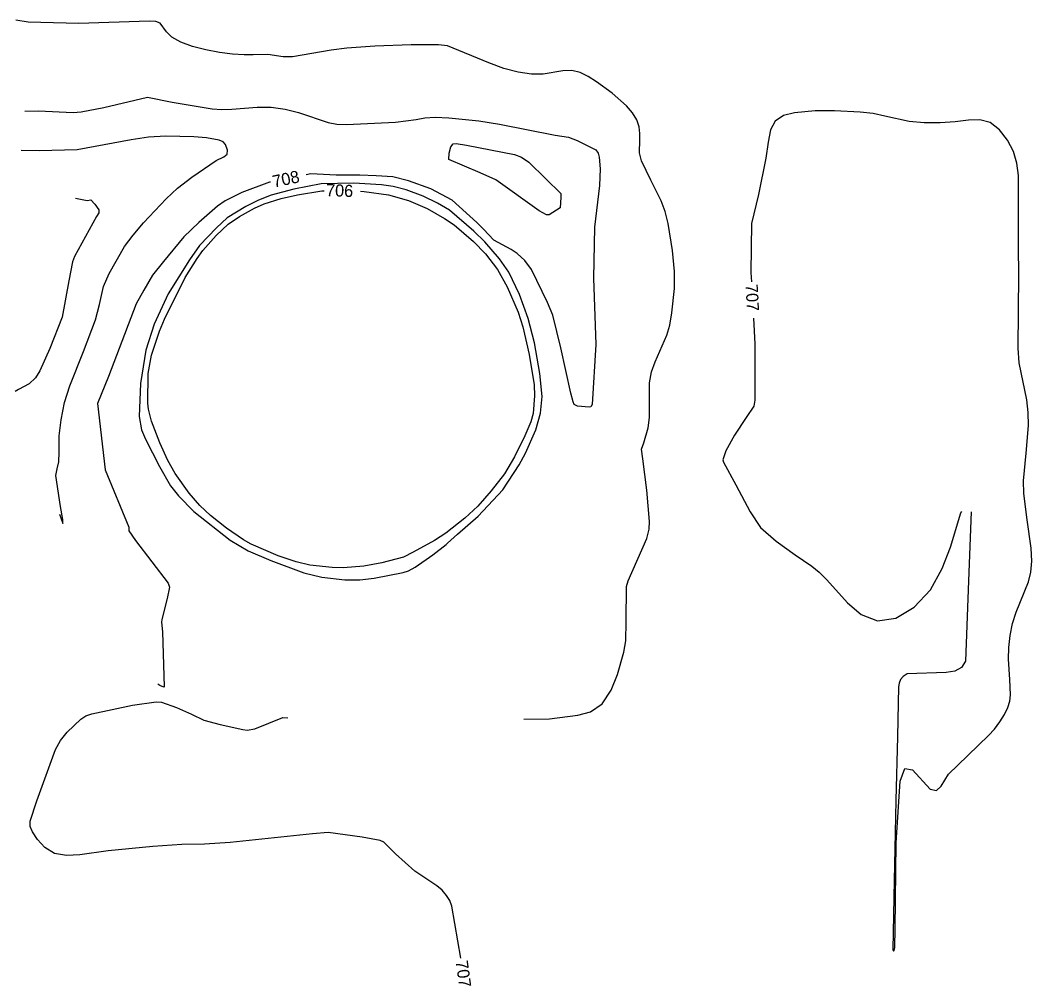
# Model space of a CAD drawing. Extents: x -291892836 to 2945206, y -477993085 to 1832792.
# Drawn here: x 1849119 to 1849452, y 544307.9 to 544625.9 of the extents above; entities that cross this region are included whole.
import ezdxf

# ---------------------------------------------------------------- set-up
doc = ezdxf.new("R2010")
doc.units = 0
doc.layers.add('DT_X_Contour_Minor', color=7, linetype='Continuous')
doc.layers.add('Level 19', color=7, linetype='Continuous')

msp = doc.modelspace()

# ---------------------------------------------------------------- linework, layer by layer
at = {"layer": 'DT_X_Contour_Minor'}
for points in [[(1849284.82, 544395.63), (1849293.23, 544395.79), (1849302.58, 544396.95), (1849306.71, 544398.13), (1849310.6, 544400.76), (1849313.6, 544405.19), (1849315.7, 544410.37), (1849317.7, 544417.73), (1849318.36, 544421.49), (1849318.47, 544427.89), (1849318.65, 544439.34), (1849319.14, 544441.24), (1849325.33, 544455.16), (1849326.1, 544458.21), (1849326.23, 544460.8), (1849325.34, 544471.14), (1849323.98, 544481.36), (1849323.6, 544484.56), (1849324.27, 544486.69), (1849325.76, 544491.63), (1849326.22, 544495.02), (1849326.17, 544506.42), (1849326.88, 544510.03), (1849328.05, 544513.38), (1849331.85, 544522.09), (1849332.83, 544525.42), (1849333.59, 544529.45), (1849334.43, 544537.52), (1849334.43, 544543.14), (1849333.73, 544550.07), (1849332.33, 544558.9), (1849331.31, 544562.82), (1849330.04, 544566.36), (1849326.66, 544573.22), (1849323.58, 544579.59), (1849322.95, 544582.14), (1849322.96, 544586.46), (1849323.01, 544588.59), (1849322.76, 544590.79), (1849322, 544593.05), (1849320.58, 544595.35), (1849318.62, 544597.63), (1849313.89, 544601.87), (1849308.71, 544605.61), (1849306.05, 544607.31), (1849303.34, 544608.65), (1849300.57, 544609.32), (1849297.71, 544609.17), (1849291.21, 544608.07), (1849287.32, 544608.09), (1849282.99, 544608.73), (1849278.28, 544609.99), (1849273.32, 544611.81), (1849259.65, 544617.42), (1849256.7, 544617.72), (1849247.77, 544617.77), (1849235.73, 544617.36), (1849226.6, 544616.68), (1849221.39, 544616.03), (1849208.7, 544613.74), (1849205.6, 544613.79), (1849200.56, 544614.52), (1849195.76, 544614.49), (1849192.73, 544614.47), (1849188.96, 544614.71), (1849184.67, 544615.26), (1849180.15, 544616.11), (1849175.76, 544617.25), (1849171.89, 544618.65), (1849168.94, 544620.26), (1849167.16, 544622.01), (1849165.1, 544624.86), (1849163.64, 544625.46), (1849161.49, 544625.59), (1849138.35, 544624.8), (1849121.69, 544625.24), (1849117.53, 544625.85)], [(1849120.55, 544595.93), (1849125.06, 544596.02), (1849136.47, 544595.49), (1849139.05, 544595.65), (1849146.55, 544597.15), (1849160.89, 544600.49), (1849169.02, 544598.87), (1849182.19, 544596.7), (1849185.38, 544596.44), (1849188.68, 544596.51), (1849197.02, 544597.25), (1849201.67, 544597.23), (1849206.28, 544596.57), (1849210.61, 544595.45), (1849220.43, 544592.2), (1849223.26, 544591.67), (1849226.41, 544591.53), (1849242.6, 544592.31), (1849249.38, 544593.18), (1849252.18, 544593.67), (1849255.6, 544593.92), (1849260.16, 544593.76), (1849269.95, 544592.75), (1849276.77, 544591.67), (1849295.18, 544588.02), (1849299.54, 544587.32), (1849302.41, 544586.24), (1849308.49, 544583.12), (1849309.29, 544582.09), (1849309.67, 544580.8), (1849309.91, 544576.88), (1849309.72, 544571.4), (1849308.03, 544557.69), (1849307.71, 544540.87), (1849308.48, 544519.11), (1849307.34, 544499.25), (1849306.85, 544498.52), (1849306.29, 544498.44), (1849302.46, 544498.71), (1849301.39, 544499.26), (1849301.04, 544500.22), (1849300.33, 544503.07), (1849296.98, 544517.91), (1849294.35, 544528.74), (1849292.66, 544532.85), (1849287.33, 544543.74), (1849285.1, 544546.7), (1849282.62, 544549), (1849280.7, 544550.38), (1849274.93, 544553.46), (1849271.5, 544557.06), (1849269.29, 544559.23), (1849261.22, 544566.61), (1849254.16, 544570.28), (1849246.87, 544572.97), (1849241.72, 544574.23), (1849236.17, 544574.64), (1849230.86, 544574.83), (1849223.04, 544574.87), (1849214.68, 544575.26), (1849213.13, 544574.95)], [(1849406.28, 544319.87), (1849406.47, 544319.24), (1849406.78, 544319.46), (1849406.94, 544320.48), (1849407.05, 544326.7), (1849407.38, 544354.94), (1849408.72, 544375.28), (1849410.24, 544379.48), (1849412.77, 544378.95), (1849418.63, 544372.65), (1849420.7, 544372.16), (1849422.19, 544373.63), (1849424.66, 544377.54), (1849427.65, 544380.51), (1849437.83, 544390.25), (1849439.77, 544392.42), (1849441.55, 544394.8), (1849443.05, 544397.23), (1849444.16, 544399.55), (1849444.79, 544401.64), (1849445.02, 544403.69), (1849444.78, 544408.7), (1849444.4, 544415.41), (1849444.48, 544419.26), (1849444.87, 544423.25), (1849445.68, 544427.19), (1849446.93, 544430.93), (1849451.01, 544440.87), (1849451.76, 544444.08), (1849452.03, 544447.72), (1849451.82, 544451.98), (1849450.55, 544461.3), (1849449.44, 544469.95), (1849449.32, 544474.22), (1849450.15, 544483.23), (1849450.92, 544492.34), (1849450.86, 544496.7), (1849450.39, 544500.86), (1849447.84, 544513.07), (1849447.58, 544517.85), (1849447.83, 544542.2), (1849447.67, 544550.93), (1849447.67, 544574.76), (1849447.14, 544578.82), (1849445.97, 544582.57), (1849443.99, 544586.37), (1849441.36, 544589.78), (1849438.29, 544592.14), (1849434.94, 544593.03), (1849431.2, 544592.89), (1849426.87, 544592.39), (1849421.86, 544592.08), (1849416.63, 544592.11), (1849411.71, 544592.53), (1849403.7, 544594.26), (1849399.82, 544595.09), (1849395.54, 544595.61), (1849387.13, 544595.97), (1849380.7, 544595.96), (1849373.89, 544595.38), (1849370.35, 544594.45), (1849367.57, 544592.66), (1849366.01, 544589.74), (1849365.21, 544585.66), (1849364.49, 544580.47), (1849362.03, 544568.43), (1849359.81, 544558.91), (1849359.57, 544542.77), (1849359.74, 544539.7)], [(1849131.9, 544463.17), (1849133.09, 544460.09), (1849133.08, 544461.45), (1849132.26, 544465.76), (1849130.72, 544475.93), (1849131.2, 544478.17), (1849131.75, 544480.41), (1849131.89, 544483.64), (1849131.79, 544489), (1849132.49, 544494.2), (1849133.65, 544499.95), (1849135.35, 544505.44), (1849139.88, 544516.74), (1849143.84, 544527.23), (1849145.14, 544532.2), (1849146.49, 544538.15), (1849148.29, 544542.47), (1849153.37, 544551.35), (1849156.17, 544555.11), (1849159.63, 544559.15), (1849167.1, 544567.07), (1849170.77, 544570.52), (1849175.53, 544574.14), (1849183.48, 544579.61), (1849186.1, 544580.82), (1849187.2, 544581.77), (1849187.24, 544583.02), (1849186.64, 544584.94), (1849185.83, 544585.8), (1849184.57, 544586.39), (1849180.34, 544587.14), (1849176.18, 544587.47), (1849166.96, 544587.63), (1849161.26, 544587.29), (1849155.57, 544586.5), (1849137.8, 544583.12), (1849125.22, 544582.89), (1849119.35, 544582.99)], [(1849296.76, 544564.12), (1849293.19, 544561.78), (1849292.23, 544561.76), (1849289.89, 544563.06), (1849275.59, 544573.24), (1849270.49, 544575.58), (1849260.09, 544580.03), (1849260.29, 544582.02), (1849260.79, 544584.17), (1849261.59, 544585.14), (1849262.53, 544585.3), (1849265.92, 544584.74), (1849281.7, 544581.62), (1849284.08, 544580.71), (1849286.42, 544579.11), (1849292.1, 544573.63), (1849297.02, 544568.74), (1849296.97, 544567.46), (1849296.76, 544564.12)], [(1849201.37, 544572.53), (1849201.1, 544572.47), (1849191.98, 544569.08), (1849186.47, 544566.32), (1849183.96, 544564.63), (1849177.83, 544559.27), (1849172.87, 544554.49), (1849166.23, 544546.39), (1849162.59, 544541.84), (1849159.67, 544536.94), (1849157.24, 544532.4), (1849150.7, 544515.49), (1849148.1, 544508.57), (1849144.43, 544499.65), (1849147.03, 544477.79), (1849154.73, 544458.88), (1849154.73, 544457.74), (1849156.95, 544454.56), (1849167.78, 544440.44), (1849168.2, 544439.1), (1849167.44, 544435.38), (1849165.64, 544428.47), (1849165.51, 544427.65), (1849165.89, 544424.46), (1849166.41, 544406.33), (1849166.34, 544406.21), (1849164.94, 544406.72), (1849164.37, 544407.23)], [(1849259.25, 544453.2), (1849259.7, 544453.63), (1849263.02, 544456.55), (1849269.76, 544462.5), (1849277.89, 544471.25), (1849283.25, 544479.48), (1849285.35, 544483.29), (1849288.76, 544490.92), (1849290.33, 544496.5), (1849290.8, 544501.95), (1849290.05, 544509.55), (1849288.29, 544519.62), (1849286.27, 544527.62), (1849283.43, 544535.57), (1849279.85, 544542.91), (1849276.81, 544547.22), (1849272.01, 544552.84), (1849268.37, 544556.41), (1849260.33, 544563.31), (1849256.41, 544565.58), (1849251.71, 544567.88), (1849246.1, 544570.01), (1849241.75, 544571.08), (1849237.94, 544571.66), (1849228.84, 544572.24), (1849218.14, 544571.96), (1849209.05, 544570.21), (1849201.6, 544568.21), (1849197.5, 544566.6), (1849193.26, 544564.52), (1849187.1, 544560.75), (1849183.69, 544557.47), (1849178.09, 544551.63), (1849174.8, 544546.91), (1849167.68, 544535.75), (1849163.12, 544525.8), (1849160.33, 544517.15), (1849158.62, 544506.22), (1849158.13, 544495.34), (1849158.93, 544490.99), (1849160.3, 544487.86), (1849164.86, 544478.9), (1849168.54, 544472.5), (1849171.13, 544469.25), (1849176.15, 544464.11), (1849188.13, 544454.6), (1849194.02, 544451.08), (1849201.54, 544447.96), (1849212.36, 544443.91), (1849218.37, 544442.48), (1849225.9, 544441.56), (1849230.79, 544441.59), (1849235.59, 544442.08), (1849245.13, 544443.99), (1849246.86, 544444.57), (1849248.99, 544445.72), (1849254.85, 544449.85), (1849259.25, 544453.2)], [(1849245.16, 544449.07), (1849238.05, 544447.19), (1849232.19, 544446.09), (1849225.31, 544445.51), (1849221.68, 544445.6), (1849214.32, 544446.36), (1849209.82, 544447.45), (1849203.98, 544449.48), (1849195.09, 544453.31), (1849192.55, 544454.75), (1849186.94, 544458.63), (1849181.68, 544462.72), (1849178.18, 544466.05), (1849174.62, 544470.13), (1849170.02, 544476.56), (1849167.64, 544480.89), (1849164.93, 544486.67), (1849162.25, 544493.85), (1849161.29, 544497.78), (1849161.05, 544499.75), (1849161.11, 544509.53), (1849162.26, 544515.52), (1849164.87, 544523.46), (1849166.49, 544527.45), (1849173.37, 544541.18), (1849177.3, 544547.36), (1849179.18, 544550.02), (1849183.52, 544554.97), (1849187.5, 544558.65), (1849191.16, 544561.2), (1849196.17, 544563.99), (1849199.32, 544565.44), (1849204.9, 544567.1), (1849210.3, 544568.35), (1849218.3, 544569.7), (1849219.07, 544569.72)], [(1849137.25, 544567.23), (1849141.03, 544566.48), (1849142.29, 544566.71), (1849143.59, 544565.25), (1849144.87, 544563.46), (1849144.94, 544562.44), (1849144.14, 544561.24), (1849136.91, 544547.99), (1849136.28, 544546.32), (1849135.07, 544540.01), (1849132.81, 544528.04), (1849128.76, 544517.74), (1849125.43, 544510.36), (1849124.01, 544508.09), (1849121.96, 544506.14), (1849118.46, 544504.19), (1849117.38, 544503.62)], [(1849231.07, 544569.51), (1849232.3, 544569.46), (1849240.25, 544568.3), (1849246.88, 544566.47), (1849252.94, 544563.82), (1849258.72, 544560.57), (1849261.83, 544558.46), (1849268.2, 544553), (1849272.23, 544548.92), (1849276.13, 544543.72), (1849279.37, 544538.02), (1849282.93, 544529.73), (1849284.5, 544524.89), (1849286.62, 544515.76), (1849288.22, 544505.81), (1849288.33, 544502.18), (1849287.84, 544496.31), (1849287.11, 544493.65), (1849285.2, 544488.95), (1849281.74, 544482.06), (1849278.45, 544476.48), (1849274.09, 544470.85), (1849269.65, 544465.87), (1849265.36, 544461.88), (1849259.1, 544456.93), (1849255.4, 544454.47), (1849248.38, 544450.7), (1849245.16, 544449.07)], [(1849360.4, 544527.72), (1849360.86, 544519.25), (1849360.9, 544500.71), (1849360.58, 544498.71), (1849358.03, 544495.06), (1849354.17, 544489.2), (1849351.31, 544484.08), (1849350.34, 544481.11), (1849350.58, 544480.33), (1849354.56, 544472.8), (1849359.33, 544463.93), (1849362.72, 544458.81), (1849367.84, 544454.33), (1849374.09, 544449.79), (1849379.61, 544446.05), (1849382.05, 544444.05), (1849384.59, 544441.56), (1849391.32, 544434.02), (1849395.87, 544430.14), (1849401.23, 544428.08), (1849407.27, 544428.99), (1849413.35, 544432.61), (1849418.66, 544438.29), (1849422.59, 544445.28), (1849425.28, 544452.37), (1849428.72, 544463.66), (1849428.96, 544464.05)], [(1849432.06, 544463.97), (1849431.22, 544441.19), (1849430.18, 544414.81), (1849428.95, 544412.67), (1849426.73, 544411.51), (1849423.86, 544411.08), (1849411.06, 544410.57), (1849409.72, 544409.71), (1849408.87, 544408.7), (1849408.33, 544407.49), (1849408.18, 544406.35), (1849407.79, 544390), (1849407.3, 544368.91), (1849406.73, 544342.59), (1849406.28, 544319.87)], [(1849264.09, 544316.96), (1849261.15, 544334.06), (1849260.44, 544335.92), (1849259.38, 544337.66), (1849257.94, 544339.32), (1849256.18, 544340.83), (1849248.89, 544345.62), (1849242.6, 544351.34), (1849238.75, 544355.13), (1849237.5, 544355.76), (1849231.61, 544356.79), (1849220.38, 544358.33), (1849215.25, 544357.96), (1849188.15, 544355.01), (1849179.71, 544354.54), (1849172.26, 544354.39), (1849162.72, 544353.73), (1849147.94, 544352.29), (1849138.63, 544351.04), (1849134.24, 544350.78), (1849130.34, 544351.48), (1849127.13, 544353.44), (1849124.7, 544356.07), (1849123.09, 544358.56), (1849122.32, 544360.37), (1849122.35, 544362.13), (1849124.53, 544368.79), (1849130.66, 544385.71), (1849132.3, 544388.62), (1849134.46, 544391.38), (1849138.96, 544395.68), (1849140.64, 544396.79), (1849142.55, 544397.48), (1849155.95, 544400.28), (1849163.83, 544401.42), (1849165.57, 544401.3), (1849170.45, 544399.47), (1849175.45, 544397.28), (1849179.51, 544395.34), (1849184.89, 544393.97), (1849192.28, 544392.27), (1849193.77, 544392.07), (1849196.22, 544392.5), (1849205.53, 544396.2), (1849207.07, 544396.16)]]:
    msp.add_lwpolyline(points, dxfattribs=at)

# ---------------------------------------------------------------- texts
at = {"layer": 'Level 19'}
for s, rotation, p in [('708', 12.0894, (1849202.54, 544570.68)), ('706', 357.772, (1849219.64, 544567.95)), ('707', 273.0831, (1849357.8, 544538.86)), ('707', 277.7871, (1849262.36, 544315.97))]:
    msp.add_text(s, height=4, rotation=rotation, dxfattribs=at).set_placement(p)

doc.saveas('drawing.dxf')
